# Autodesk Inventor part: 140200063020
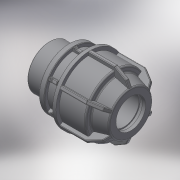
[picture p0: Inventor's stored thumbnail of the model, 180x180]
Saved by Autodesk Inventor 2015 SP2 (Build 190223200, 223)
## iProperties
Created: 2017-08
Part Number: 140200063020
Material: Generic
Description: PLASSON L.14 MALE ADAPTOR (SILVER) 63-2''
Document SubType Name: Modeling
Designer: KIM
Density: 1 g/cm^3
Appearance: Default
Author: KIM
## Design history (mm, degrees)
derived "140200.ipt"
feature "Solid1::140200.ipt"
tag "TaggingFeature1"
body "Solid1"
other parameters: "d1" = 63, "d2" = 94, "d4" = 15 deg, "d5" = 62.04, "d6" = 20.4732, "d10" = 106, "d16" = 64.26, "d17" = 4.7, "d18" = 122, "d19" = 7.8, "d21" = 7.8, "d22" = 71.5368, "d24" = 4.7, "d25" = 95.4, "d26" = 79.5, "d27" = 4.7, "d28" = 135 deg, "d29" = 2.82, "d31" = 3.15, "d44" = 1.26, "d45" = 1.89, "d46" = 150 deg, "d49" = 5.3, "d50" = 0, "d51" = 3.18, "d52" = 2.12, "d53" = 45 deg, "d54" = 21, "d55" = 8.4, "d56" = 5.3, "d57" = 0, "d58" = 1.89, "d59" = 1.26, "d61" = 360 deg, "d63" = 59.614, "d64" = 50.4, "d65" = 26, "d66" = 80.4789, "d_" = 63, "R_" = 59.614, "E_" = 106, "H_" = 122, "l_" = 94, "l_2" = 26
